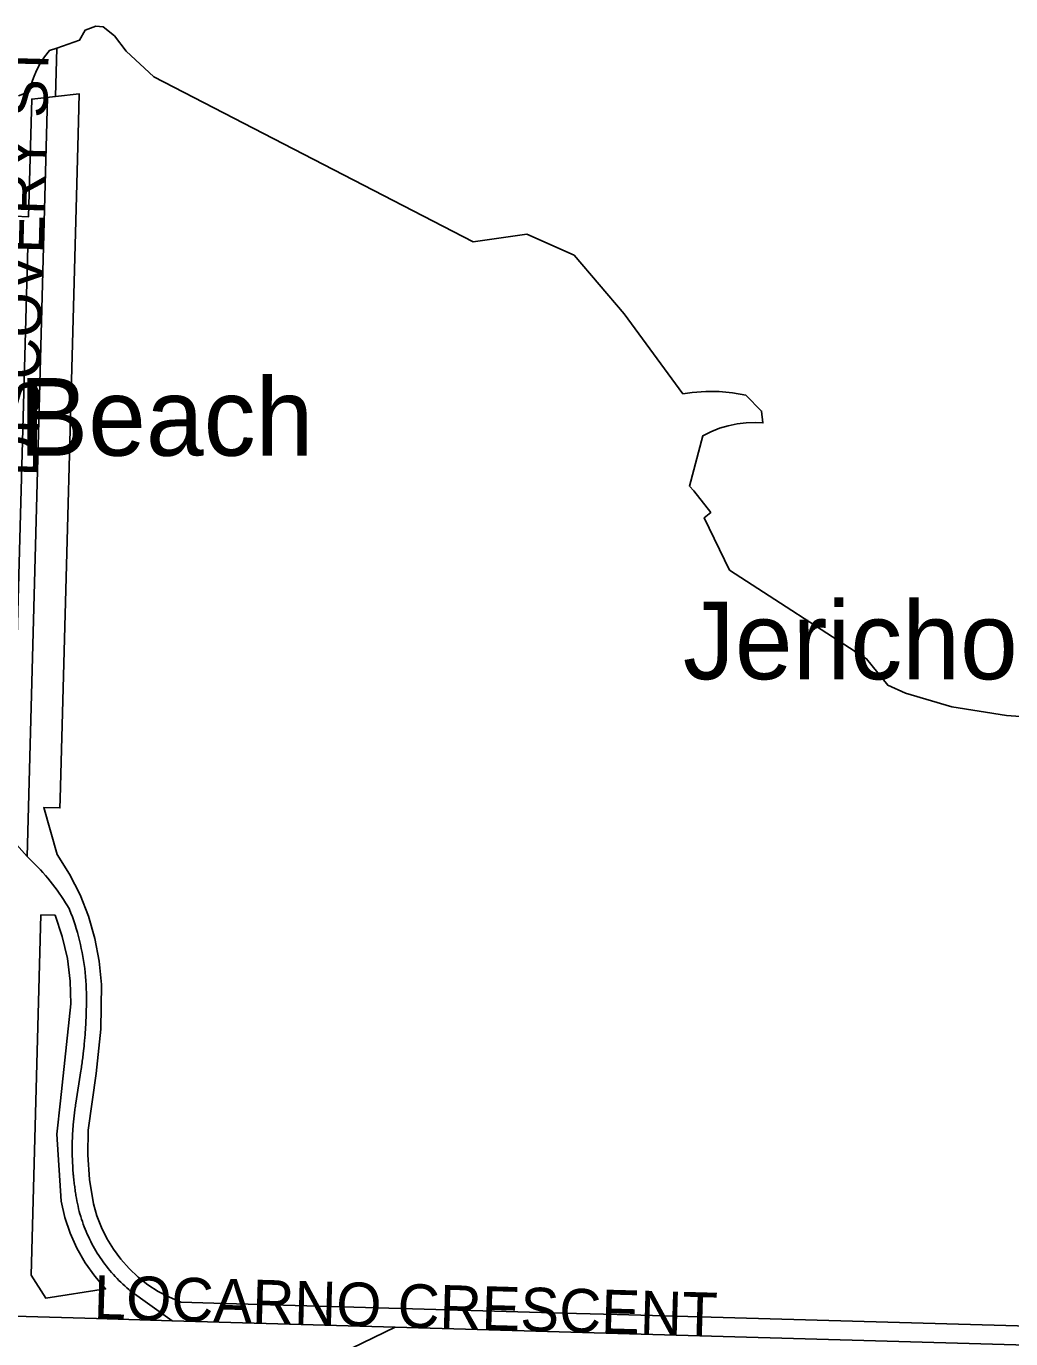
# Model space of a CAD drawing. Extents: x 482780 to 486928, y 5455974 to 5459836.
# Drawn here: x 485252 to 485885, y 5457356 to 5458200 of the extents above; entities that cross this region are included whole.
import ezdxf

# ---------------------------------------------------------------- set-up
doc = ezdxf.new("R2010")
doc.units = 0
for name, color, linetype in [('ParkLabels', 7, 'Continuous'), ('Parks', 7, 'Continuous'), ('StreetNames', 7, 'Continuous'), ('Streets', 7, 'Continuous')]:
    doc.layers.add(name, color=color, linetype=linetype)

msp = doc.modelspace()

# ---------------------------------------------------------------- linework, layer by layer
at = {"layer": 'Parks'}
for points in [[(486033.88, 5457359.78), (485806.08, 5457366.24), (485631.83, 5457371.19), (485605.68, 5457371.93), (485379.48, 5457378.35), (485351.08, 5457379.16), (485343.7, 5457382.26), (485336.62, 5457386.01), (485329.91, 5457390.37), (485323.61, 5457395.31), (485317.77, 5457400.79), (485312.45, 5457406.77), (485307.68, 5457413.2), (485303.5, 5457420.03), (485299.95, 5457427.21), (485297.05, 5457434.67), (485294.82, 5457442.36), (485292.27, 5457458.06), (485291.17, 5457473.92), (485291.52, 5457489.82), (485296.53, 5457526.36), (485299.69, 5457554.94), (485300.05, 5457583.69), (485298.64, 5457598.54), (485295.86, 5457613.18), (485291.71, 5457627.51), (485286.25, 5457641.38), (485279.52, 5457654.68), (485271.57, 5457667.3), (485262.93, 5457697.51), (485273.33, 5457697.27), (485273.49, 5457703.12), (485284.34, 5458106.92), (485285.21, 5458139.12), (485285.68, 5458156.77), (485270.4, 5458155.15), (485271.24, 5458186.34), (485285.95, 5458191.45), (485289.43, 5458197.89), (485296.37, 5458200.36), (485301.03, 5458200.02), (485308.43, 5458194.11), (485315.9, 5458184.41), (485333.72, 5458167.89), (485539.15, 5458061.53), (485573.76, 5458066.58), (485604.14, 5458053.09), (485636.51, 5458015.28), (485674.2, 5457963.67), (485680.26, 5457964.61), (485688.9, 5457965.29), (485697.56, 5457965.22), (485706.18, 5457964.4), (485714.71, 5457962.82), (485724.84, 5457952.7), (485725.68, 5457945.1), (485720.94, 5457945.33), (485715.03, 5457945.16), (485709.18, 5457944.47), (485703.4, 5457943.27), (485697.75, 5457941.57), (485692.26, 5457939.39), (485686.99, 5457936.74), (485678.44, 5457904.28), (485681.22, 5457901.36), (485692.13, 5457887.43), (485687.99, 5457883.98), (485704.28, 5457850.34), (485792.45, 5457793.31), (485806.02, 5457776.18), (485817.44, 5457771.21), (485847.28, 5457762.38), (485882.47, 5457756.67), (485933.78, 5457752.98)], [(485246.55, 5458155.64), (485253.69, 5458158.37), (485254.63, 5458162.41), (485256.22, 5458167.25), (485258.21, 5458171.93), (485260.61, 5458176.43), (485263.39, 5458180.69), (485266.53, 5458184.7), (485271.24, 5458186.34), (485270.4, 5458155.15), (485255.13, 5458153.52), (485253.08, 5458077.77), (485244.18, 5458078.02)], [(485243.68, 5458058.87), (485252.57, 5458058.62), (485242.83, 5457698.06)]]:
    msp.add_lwpolyline(points, dxfattribs=at)
msp.add_lwpolyline([(485274.02, 5457444.12), (485276.42, 5457433.7), (485279.82, 5457423.56), (485284.18, 5457413.8), (485289.48, 5457404.51), (485295.65, 5457395.78), (485302.64, 5457387.69), (485264.23, 5457381.66), (485254.83, 5457396.56), (485261.08, 5457628.41), (485270.13, 5457628.21), (485274.83, 5457614.43), (485278.1, 5457600.24), (485279.91, 5457585.78), (485280.25, 5457571.22), (485273.58, 5457508.71), (485271.35, 5457487.21)], close=True, dxfattribs=at)
at = {"layer": 'Streets'}
for points in [[(485265.3, 5458154.61), (485252.11, 5457665.92)], [(485221.37, 5457700.44), (485252.11, 5457665.92), (485253.89, 5457664.28), (485255.64, 5457662.6), (485257.37, 5457660.9), (485259.06, 5457659.16), (485260.73, 5457657.4), (485262.36, 5457655.61), (485263.96, 5457653.79), (485265.53, 5457651.94), (485267.07, 5457650.06), (485268.57, 5457648.16), (485270.04, 5457646.23), (485271.48, 5457644.28), (485272.88, 5457642.3), (485274.25, 5457640.3), (485275.58, 5457638.28), (485276.88, 5457636.23), (485278.14, 5457634.16), (485279.36, 5457632.06), (485279.42, 5457631.96), (485280.38, 5457629.51), (485281.3, 5457627.05), (485282.17, 5457624.57), (485283, 5457622.08), (485283.79, 5457619.57), (485284.53, 5457617.05), (485285.23, 5457614.52), (485285.89, 5457611.97), (485286.5, 5457609.41), (485287.06, 5457606.85), (485287.58, 5457604.27), (485288.06, 5457601.69), (485288.49, 5457599.09), (485288.87, 5457596.49), (485289.21, 5457593.89), (485289.51, 5457591.27), (485289.75, 5457588.66), (485289.96, 5457586.04), (485290.11, 5457583.41), (485290.22, 5457580.79), (485290.29, 5457578.16), (485290.3, 5457577.52), (485290.31, 5457576.45), (485290.32, 5457575.37), (485290.32, 5457574.35), (485290.33, 5457573.28), (485290.32, 5457572.2), (485290.32, 5457571.18), (485290.31, 5457570.07), (485290.29, 5457569.01), (485290.27, 5457567.98), (485290.24, 5457566.58), (485290.23, 5457565.88), (485290.19, 5457564.78), (485290.16, 5457563.73), (485290.15, 5457563.47), (485290.1, 5457562.05), (485290.04, 5457560.57), (485289.99, 5457559.5), (485289.94, 5457558.42), (485289.88, 5457557.43), (485289.82, 5457556.41), (485289.75, 5457555.27), (485289.68, 5457554.19), (485289.61, 5457553.17), (485289.53, 5457552.11), (485289.43, 5457550.85), (485289.35, 5457549.82), (485289.29, 5457548.95), (485289.18, 5457547.78), (485289.1, 5457546.81), (485288.99, 5457545.72), (485288.87, 5457544.48), (485288.79, 5457543.65), (485288.67, 5457542.6), (485288.46, 5457540.61), (485288.45, 5457540.51), (485288.32, 5457539.44), (485288.19, 5457538.38), (485288.06, 5457537.33), (485287.93, 5457536.31), (485287.8, 5457535.3), (485287.66, 5457534.22), (485287.51, 5457533.11), (485287.35, 5457532.06), (485287.2, 5457531.04), (485287.1, 5457530.35), (485286.89, 5457528.96), (485286.73, 5457527.93), (485283.53, 5457507.17), (485283.37, 5457506.19), (485283.23, 5457505.29), (485283.09, 5457504.28), (485282.95, 5457503.33), (485282.84, 5457502.42), (485282.71, 5457501.42), (485282.58, 5457500.46), (485282.47, 5457499.5), (485282.35, 5457498.55), (485282.25, 5457497.64), (485282.24, 5457497.52), (485281.97, 5457494.78), (485281.97, 5457494.75), (485281.89, 5457493.79), (485281.8, 5457492.78), (485281.73, 5457491.87), (485281.66, 5457490.91), (485281.6, 5457489.95), (485281.54, 5457488.99), (485281.48, 5457487.97), (485281.43, 5457487.06), (485281.39, 5457486.1), (485281.34, 5457485.14), (485281.31, 5457484.17), (485281.27, 5457483.2), (485281.26, 5457482.31), (485281.24, 5457481.29), (485281.22, 5457480.31), (485281.21, 5457479.34), (485281.2, 5457478.38), (485281.2, 5457477.42), (485281.2, 5457476.45), (485281.21, 5457475.54), (485281.23, 5457474.55), (485281.25, 5457473.27), (485281.26, 5457472.6), (485281.29, 5457471.67), (485281.35, 5457470.14), (485281.37, 5457469.75), (485281.42, 5457468.77), (485281.51, 5457466.95), (485281.54, 5457466.36), (485281.6, 5457465.41), (485281.63, 5457464.93), (485281.7, 5457463.97), (485281.83, 5457462.3), (485281.85, 5457462.05), (485281.91, 5457461.37), (485281.97, 5457460.75), (485282.09, 5457459.42), (485282.21, 5457458.21), (485282.31, 5457457.3), (485282.43, 5457456.29), (485282.54, 5457455.33), (485282.66, 5457454.42), (485282.79, 5457453.42), (485282.91, 5457452.46), (485283.03, 5457451.56), (485283.18, 5457450.61), (485283.33, 5457449.6), (485283.47, 5457448.65), (485283.62, 5457447.7), (485283.9, 5457445.99), (485284.21, 5457444.3), (485284.55, 5457442.6), (485284.92, 5457440.92), (485285.32, 5457439.24), (485285.75, 5457437.56), (485286.2, 5457435.9), (485286.69, 5457434.24), (485287.2, 5457432.59), (485287.74, 5457430.95), (485288.32, 5457429.33), (485288.92, 5457427.71), (485289.54, 5457426.1), (485290.2, 5457424.5), (485290.88, 5457422.92), (485291.6, 5457421.34), (485292.33, 5457419.78), (485293.1, 5457418.24), (485293.89, 5457416.7), (485294.71, 5457415.18), (485295.56, 5457413.68), (485296.43, 5457412.19), (485297.33, 5457410.71), (485298.25, 5457409.25), (485299.2, 5457407.81), (485300.18, 5457406.38), (485301.17, 5457404.98), (485302.2, 5457403.59), (485303.24, 5457402.21), (485304.32, 5457400.86), (485305.41, 5457399.52), (485306.53, 5457398.21), (485307.67, 5457396.91), (485308.83, 5457395.63), (485310.02, 5457394.38), (485311.22, 5457393.14), (485312.45, 5457391.93), (485313.7, 5457390.74), (485314.97, 5457389.57), (485316.26, 5457388.42), (485317.57, 5457387.29), (485318.24, 5457386.73), (485345.46, 5457367.15), (485489.13, 5457363.05)], [(485244.13, 5457370.04), (485296.86, 5457368.53), (485345.46, 5457367.15)], [(485426.1, 5457332.63), (485489.13, 5457363.05), (486129.92, 5457344.83)]]:
    msp.add_lwpolyline(points, dxfattribs=at)

# ---------------------------------------------------------------- texts
at = {"layer": 'ParkLabels'}
for s, p in [('Locarno Park Beach', (484830.58, 5457923.96)), ('Jericho Beach  Park', (485674.23, 5457780.07))]:
    msp.add_text(s, height=50, dxfattribs=at).set_placement(p)
at = {"layer": 'StreetNames'}
for s, rotation, p in [('DISCOVERY ST', 88.454, (485258.7, 5457910.26)), ('LOCARNO CRESCENT', 358.36856, (485294.79, 5457368.59))]:
    msp.add_text(s, height=28, rotation=rotation, dxfattribs=at).set_placement(p)

doc.saveas('drawing.dxf')
